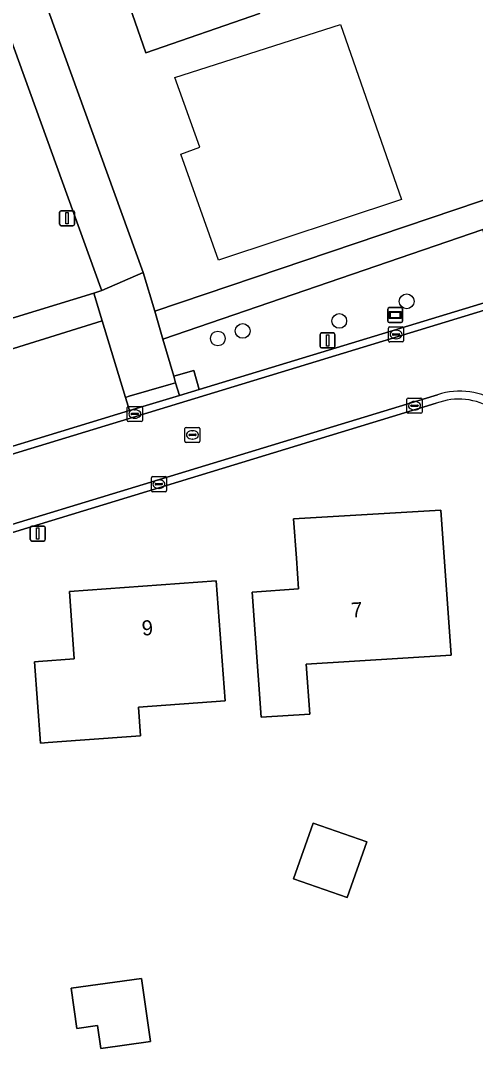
# Model space of a CAD drawing. Extents: x 162661 to 163484, y 380247 to 381230.
# Drawn here: x 162984 to 163014.3, y 380733.3 to 380801.7 of the extents above; entities that cross this region are included whole.
import ezdxf

# ---------------------------------------------------------------- set-up
doc = ezdxf.new("R2010")
doc.units = 0
for name, color, linetype in [('IMGEO_Berm_halfverhard', 7, 'Continuous'), ('IMGEO_Boom', 7, 'Continuous'), ('IMGEO_Erf', 7, 'Continuous'), ('IMGEO_Groenvoorziening', 7, 'Continuous'), ('IMGEO_Kolk', 7, 'Continuous'), ('IMGEO_Lichtmast', 7, 'Continuous'), ('IMGEO_Pand', 7, 'Continuous'), ('IMGEO_Pand_nummerreeks', 7, 'Continuous'), ('IMGEO_Pand_vergunning_verleend', 7, 'Continuous'), ('IMGEO_Parkeervlak_open', 7, 'Continuous'), ('IMGEO_Rijbaan_lokaal_gesloten', 7, 'Continuous'), ('IMGEO_Rijbaan_lokaal_open', 7, 'Continuous'), ('IMGEO_Rioolput', 7, 'Continuous'), ('IMGEO_Voetpad_open', 7, 'Continuous'), ('IMGEO_Wegwijzer', 7, 'Continuous')]:
    doc.layers.add(name, color=color, linetype=linetype)

msp = doc.modelspace()

# ---------------------------------------------------------------- linework, layer by layer
at = {"layer": 'IMGEO_Berm_halfverhard'}
msp.add_lwpolyline([(162995.544, 380778.396), (162994.204, 380778.017), (162994.332, 380777.579), (162994.583, 380776.73), (162995.902, 380777.131)], close=True, dxfattribs=at)
at = {"layer": 'IMGEO_Boom'}
for centre in [(163009.697, 380782.988), (163005.212, 380781.684), (162997.137, 380780.52), (162998.789, 380781.023)]:
    msp.add_circle(centre, 0.489, dxfattribs=at)
at = {"layer": 'IMGEO_Erf'}
for points in [[(162926.406, 380762.393), (162971.79, 380776.161), (162971.978, 380776.218), (162971.296, 380778.555), (162965.296, 380803.494), (162959.948, 380825.491), (162975.656, 380830.504), (162983.99, 380807.505), (162992.18, 380784.912), (162992.937, 380782.334), (163021.239, 380791.885)], [(163011.662, 380776.211), (162963.124, 380761.423)]]:
    msp.add_lwpolyline(points, dxfattribs=at)
for points in [[(162989.136, 380808.763), (162998.492, 380812.004), (162999.811, 380808.197), (162998.015, 380807.574), (162999.904, 380802.121), (162992.343, 380799.502)], [(163002.362, 380765.911), (163002.176, 380768.534), (163011.975, 380769.115), (163012.657, 380759.471), (163003.019, 380758.872), (163003.253, 380755.563), (163000.013, 380755.362), (162999.426, 380763.668), (163002.505, 380763.886)], [(162984.942, 380759.04), (162985.218, 380759.06), (162987.587, 380759.234), (162987.26, 380763.699), (162997.035, 380764.416), (162997.62, 380756.437), (162991.866, 380756.015), (162992.003, 380754.12), (162987.984, 380753.826), (162985.851, 380753.67), (162985.614, 380753.653), (162985.338, 380753.632)], [(163002.177, 380744.611), (163003.478, 380748.311), (163007.042, 380747.058), (163005.741, 380743.358)], [(162987.383, 380737.337), (162992.069, 380737.992), (162992.655, 380733.798), (162989.347, 380733.336), (162989.136, 380734.853), (162987.757, 380734.66)]]:
    msp.add_lwpolyline(points, close=True, dxfattribs=at)
msp.add_arc((163013.172, 380772.236), 4.253, 3.53872, 110.80283, dxfattribs=at)
at = {"layer": 'IMGEO_Groenvoorziening'}
msp.add_lwpolyline([(162964.008, 380821.602), (162968.622, 380802.474), (162974.235, 380779.267), (162974.547, 380779.362), (162974.605, 380779.176), (162988.89, 380783.54), (162989.418, 380783.701), (162989.357, 380783.869), (162980.643, 380807.906), (162974.496, 380824.924)], dxfattribs=at)
msp.add_lwpolyline([(163016.15, 380783.294), (163014.767, 380787.754), (162993.48, 380780.484), (162994.204, 380778.017), (162995.544, 380778.396), (162995.902, 380777.131)], close=True, dxfattribs=at)
at = {"layer": 'IMGEO_Kolk'}
for p, q in [((163008.492, 380780.361), (163008.492, 380781.213)), ((163008.567, 380781.287), (163009.419, 380781.287)), ((163008.98, 380781.067), (163009.005, 380781.067)), ((163009.493, 380781.213), (163009.493, 380780.361)), ((163009.419, 380780.287), (163008.567, 380780.287)), ((163008.751, 380780.781), (163008.751, 380780.793)), ((163009.189, 380780.744), (163008.791, 380780.744)), ((163008.794, 380780.83), (163009.192, 380780.83)), ((163009.003, 380780.507), (163008.978, 380780.507)), ((163009.235, 380780.793), (163009.235, 380780.781)), ((163009.717, 380775.627), (163009.717, 380776.479)), ((163009.792, 380776.553), (163010.644, 380776.553)), ((163010.019, 380776.096), (163010.417, 380776.096)), ((163010.205, 380776.333), (163010.23, 380776.333)), ((163010.718, 380776.479), (163010.718, 380775.627)), ((162991.116, 380775.077), (162991.116, 380775.929)), ((162991.191, 380776.003), (162992.043, 380776.003)), ((162991.375, 380775.497), (162991.375, 380775.509)), ((162991.813, 380775.46), (162991.415, 380775.46)), ((162991.418, 380775.546), (162991.816, 380775.546)), ((162991.604, 380775.783), (162991.629, 380775.783)), ((162991.859, 380775.509), (162991.859, 380775.497)), ((162992.117, 380775.929), (162992.117, 380775.077)), ((163010.644, 380775.553), (163009.792, 380775.553)), ((163009.976, 380776.047), (163009.976, 380776.059)), ((163010.414, 380776.01), (163010.016, 380776.01)), ((163010.228, 380775.773), (163010.203, 380775.773)), ((163010.46, 380776.059), (163010.46, 380776.047)), ((162992.043, 380775.003), (162991.191, 380775.003)), ((162991.627, 380775.223), (162991.602, 380775.223)), ((162992.792, 380771.339), (162993.644, 380771.339)), ((162992.717, 380770.413), (162992.717, 380771.265)), ((162992.976, 380770.833), (162992.976, 380770.845)), ((162993.414, 380770.796), (162993.016, 380770.796)), ((162993.019, 380770.882), (162993.417, 380770.882)), ((162993.205, 380771.119), (162993.23, 380771.119)), ((162993.46, 380770.845), (162993.46, 380770.833)), ((162993.718, 380771.265), (162993.718, 380770.413)), ((162993.644, 380770.339), (162992.792, 380770.339)), ((162993.228, 380770.559), (162993.203, 380770.559))]:
    msp.add_line(p, q, dxfattribs=at)
for points in [[(163008.492, 380780.361), (163008.492, 380781.213)], [(163008.567, 380781.287), (163009.419, 380781.287)], [(163009.493, 380781.213), (163009.493, 380780.361)], [(163009.419, 380780.287), (163008.567, 380780.287)], [(163009.717, 380775.627), (163009.717, 380776.479)], [(163009.792, 380776.553), (163010.644, 380776.553)], [(163010.718, 380776.479), (163010.718, 380775.627)], [(162991.116, 380775.077), (162991.116, 380775.929)], [(162991.191, 380776.003), (162992.043, 380776.003)], [(162992.117, 380775.929), (162992.117, 380775.077)], [(163010.644, 380775.553), (163009.792, 380775.553)], [(162992.043, 380775.003), (162991.191, 380775.003)], [(162992.792, 380771.339), (162993.644, 380771.339)], [(162992.717, 380770.413), (162992.717, 380771.265)], [(162993.718, 380771.265), (162993.718, 380770.413)], [(162993.644, 380770.339), (162992.792, 380770.339)]]:
    msp.add_lwpolyline(points, dxfattribs=at)
for centre, radius, start, end in [((163008.569, 380781.211), 0.0765, 91.55205, 178.44795), ((163008.569, 380781.211), 0.0765, 91.55205, 178.44795), ((163009.417, 380781.211), 0.0765, 1.55205, 88.44795), ((163009.417, 380781.211), 0.0765, 1.55205, 88.44795), ((163008.569, 380780.363), 0.0765, 181.55205, 268.44795), ((163008.569, 380780.363), 0.0765, 181.55205, 268.44795), ((163008.791, 380780.79), 0.0403, 85.87752, 175.75265), ((163008.788, 380780.78), 0.0366, 178.93798, 274.71019), ((163009.192, 380780.787), 0.043, 264.86636, 352.45326), ((163009.196, 380780.792), 0.0386, 1.73085, 96.63898), ((163009.417, 380780.363), 0.0765, 271.55205, 358.44795), ((163009.417, 380780.363), 0.0765, 271.55205, 358.44795), ((163009.794, 380776.477), 0.0765, 91.55205, 178.44795), ((163009.794, 380776.477), 0.0765, 91.55205, 178.44795), ((163010.016, 380776.056), 0.0403, 85.87752, 175.75265), ((163010.421, 380776.058), 0.0386, 1.73085, 96.63898), ((163010.642, 380776.477), 0.0765, 1.55205, 88.44795), ((163010.642, 380776.477), 0.0765, 1.55205, 88.44795), ((162991.193, 380775.927), 0.0765, 91.55205, 178.44795), ((162991.193, 380775.927), 0.0765, 91.55205, 178.44795), ((162991.415, 380775.506), 0.0403, 85.87752, 175.75265), ((162991.412, 380775.496), 0.0366, 178.93798, 274.71019), ((162991.816, 380775.503), 0.043, 264.86636, 352.45326), ((162991.82, 380775.508), 0.0386, 1.73085, 96.63898), ((162992.041, 380775.927), 0.0765, 1.55205, 88.44795), ((162992.041, 380775.927), 0.0765, 1.55205, 88.44795), ((163009.794, 380775.629), 0.0765, 181.55205, 268.44795), ((163009.794, 380775.629), 0.0765, 181.55205, 268.44795), ((163010.013, 380776.046), 0.0366, 178.93798, 274.71019), ((163010.417, 380776.053), 0.043, 264.86636, 352.45326), ((163010.642, 380775.629), 0.0765, 271.55205, 358.44795), ((163010.642, 380775.629), 0.0765, 271.55205, 358.44795), ((162991.193, 380775.079), 0.0765, 181.55205, 268.44795), ((162991.193, 380775.079), 0.0765, 181.55205, 268.44795), ((162992.041, 380775.079), 0.0765, 271.55205, 358.44795), ((162992.041, 380775.079), 0.0765, 271.55205, 358.44795), ((162992.794, 380771.263), 0.0765, 91.55205, 178.44795), ((162992.794, 380771.263), 0.0765, 91.55205, 178.44795), ((162993.642, 380771.263), 0.0765, 1.55205, 88.44795), ((162993.642, 380771.263), 0.0765, 1.55205, 88.44795), ((162993.016, 380770.842), 0.0403, 85.87752, 175.75265), ((162993.013, 380770.832), 0.0366, 178.93798, 274.71019), ((162993.417, 380770.839), 0.043, 264.86636, 352.45326), ((162993.421, 380770.844), 0.0386, 1.73085, 96.63898), ((162992.794, 380770.415), 0.0765, 181.55205, 268.44795), ((162992.794, 380770.415), 0.0765, 181.55205, 268.44795), ((162993.642, 380770.415), 0.0765, 271.55205, 358.44795), ((162993.642, 380770.415), 0.0765, 271.55205, 358.44795)]:
    msp.add_arc(centre, radius, start, end, dxfattribs=at)
for centre, major_axis, ratio, start_param, end_param in [((163008.979, 380780.787), (-0.387, 0.002), 0.722429, 4.712389, 7.853982), ((163009.004, 380780.787), (-0.39, 0.002), 0.717154, 1.570796, 4.712389), ((163010.204, 380776.053), (-0.387, 0.002), 0.722429, 4.712389, 7.853982), ((163010.229, 380776.053), (-0.39, 0.002), 0.717154, 1.570796, 4.712389), ((162991.603, 380775.503), (-0.387, 0.002), 0.722429, 4.712389, 7.853982), ((162991.628, 380775.503), (-0.39, 0.002), 0.717154, 1.570796, 4.712389), ((162993.204, 380770.839), (-0.387, 0.002), 0.722429, 4.712389, 7.853982), ((162993.229, 380770.839), (-0.39, 0.002), 0.717154, 1.570796, 4.712389)]:
    msp.add_ellipse(centre, major_axis=major_axis, ratio=ratio, start_param=start_param, end_param=end_param, dxfattribs=at)
at = {"layer": 'IMGEO_Lichtmast'}
for p, q in [((162986.613, 380788.113), (162986.613, 380788.913)), ((162986.613, 380788.913), (162986.613, 380788.113)), ((162986.713, 380789.013), (162987.503, 380789.013)), ((162987.503, 380789.013), (162986.713, 380789.013)), ((162987.603, 380788.913), (162987.603, 380788.113)), ((162987.603, 380788.113), (162987.603, 380788.913)), ((162987.503, 380788.013), (162986.713, 380788.013)), ((162986.713, 380788.013), (162987.503, 380788.013)), ((163004.039, 380780.89), (163004.829, 380780.89)), ((163004.829, 380780.89), (163004.039, 380780.89)), ((163003.939, 380779.99), (163003.939, 380780.79)), ((163003.939, 380780.79), (163003.939, 380779.99)), ((163004.929, 380780.79), (163004.929, 380779.99)), ((163004.929, 380779.99), (163004.929, 380780.79)), ((163004.829, 380779.89), (163004.039, 380779.89)), ((163004.039, 380779.89), (163004.829, 380779.89)), ((162984.664, 380767.156), (162984.664, 380767.956)), ((162984.664, 380767.956), (162984.664, 380767.156)), ((162984.764, 380768.056), (162985.554, 380768.056)), ((162985.554, 380768.056), (162984.764, 380768.056)), ((162985.654, 380767.956), (162985.654, 380767.156)), ((162985.654, 380767.156), (162985.654, 380767.956)), ((162985.554, 380767.056), (162984.764, 380767.056)), ((162984.764, 380767.056), (162985.554, 380767.056))]:
    msp.add_line(p, q, dxfattribs=at)
for points in [[(162987.033, 380788.888), (162987.183, 380788.888), (162987.183, 380788.138), (162987.033, 380788.138), (162987.033, 380788.888)], [(163004.359, 380780.765), (163004.509, 380780.765), (163004.509, 380780.015), (163004.359, 380780.015), (163004.359, 380780.765)], [(162985.084, 380767.931), (162985.234, 380767.931), (162985.234, 380767.181), (162985.084, 380767.181), (162985.084, 380767.931)]]:
    msp.add_lwpolyline(points, dxfattribs=at)
for centre, start, end in [((162986.713, 380788.913), 90, 180), ((162986.713, 380788.913), 90, 180), ((162987.503, 380788.913), 0, 90), ((162987.503, 380788.913), 360, 90), ((162986.713, 380788.113), 180, 270), ((162986.713, 380788.113), 180, 270), ((162987.503, 380788.113), 270, 0), ((162987.503, 380788.113), 270, 0), ((163004.039, 380780.79), 90, 180), ((163004.039, 380780.79), 90, 180), ((163004.829, 380780.79), 0, 90), ((163004.829, 380780.79), 360, 90), ((163004.039, 380779.99), 180, 270), ((163004.039, 380779.99), 180, 270), ((163004.829, 380779.99), 270, 0), ((163004.829, 380779.99), 270, 0), ((162984.764, 380767.956), 90, 180), ((162984.764, 380767.956), 90, 180), ((162985.554, 380767.956), 0, 90), ((162985.554, 380767.956), 360, 90), ((162984.764, 380767.156), 180, 270), ((162984.764, 380767.156), 180, 270), ((162985.554, 380767.156), 270, 0), ((162985.554, 380767.156), 270, 0)]:
    msp.add_arc(centre, 0.1, start, end, dxfattribs=at)
at = {"layer": 'IMGEO_Pand'}
for points in [[(162992.343, 380799.502), (162999.904, 380802.121), (162998.015, 380807.574), (162999.811, 380808.197), (162998.492, 380812.004), (162989.136, 380808.763)], [(163011.975, 380769.115), (163002.176, 380768.534), (163002.362, 380765.911), (163002.505, 380763.886), (162999.426, 380763.668), (163000.013, 380755.362), (163003.253, 380755.563), (163003.019, 380758.872), (163012.657, 380759.471)], [(162997.035, 380764.416), (162987.26, 380763.699), (162987.587, 380759.234), (162985.218, 380759.06), (162984.942, 380759.04), (162985.338, 380753.632), (162985.614, 380753.653), (162985.851, 380753.67), (162987.984, 380753.826), (162992.003, 380754.12), (162991.866, 380756.015), (162997.62, 380756.437)], [(163002.177, 380744.611), (163005.741, 380743.358), (163007.042, 380747.058), (163003.478, 380748.311)], [(162987.383, 380737.337), (162987.757, 380734.66), (162989.136, 380734.853), (162989.347, 380733.336), (162992.655, 380733.798), (162992.069, 380737.992)]]:
    msp.add_lwpolyline(points, close=True, dxfattribs=at)
at = {"layer": 'IMGEO_Pand_vergunning_verleend'}
msp.add_lwpolyline([(162994.288, 380797.865), (163005.301, 380801.399), (163009.345, 380789.757), (162997.187, 380785.73), (162994.667, 380792.767), (162995.949, 380793.226)], close=True, dxfattribs=at)
at = {"layer": 'IMGEO_Parkeervlak_open'}
msp.add_lwpolyline([(162990.992, 380776.609), (162989.449, 380781.698), (162975.199, 380777.265), (162976.762, 380772.242), (162977.033, 380771.392), (162991.253, 380775.737)], close=True, dxfattribs=at)
at = {"layer": 'IMGEO_Rijbaan_lokaal_gesloten'}
for points in [[(163016.688, 380782.965), (162948.75, 380762.271), (162947.7, 380760.456)], [(163011.53, 380776.704), (163011.738, 380776.78)], [(162960.12, 380762.434), (162961.731, 380761.565), (163011.53, 380776.704)]]:
    msp.add_lwpolyline(points, dxfattribs=at)
msp.add_arc((163013.228, 380772.334), 4.689, 1.36553, 108.5335, dxfattribs=at)
at = {"layer": 'IMGEO_Rijbaan_lokaal_open'}
for points in [[(163017.65, 380783.769), (163016.926, 380783.534), (163016.492, 380783.398), (163016.15, 380783.294), (162995.902, 380777.131), (162994.583, 380776.73), (162991.253, 380775.737), (162977.033, 380771.392), (162973.725, 380770.368), (162972.355, 380769.952), (162970.637, 380769.431), (162949.808, 380763.113)], [(162948.75, 380762.271), (163016.688, 380782.965)], [(163011.738, 380776.78), (163011.53, 380776.704), (162961.731, 380761.565)], [(162963.124, 380761.423), (163011.662, 380776.211)]]:
    msp.add_lwpolyline(points, dxfattribs=at)
for centre, radius, start, end in [((163013.228, 380772.334), 4.689, 1.36553, 108.5335), ((163013.172, 380772.236), 4.253, 3.53872, 110.80283)]:
    msp.add_arc(centre, radius, start, end, dxfattribs=at)
at = {"layer": 'IMGEO_Rioolput'}
for p, q in [((162994.949, 380773.686), (162994.949, 380774.538)), ((162995.024, 380774.612), (162995.876, 380774.612)), ((162995.208, 380774.106), (162995.208, 380774.118)), ((162995.646, 380774.069), (162995.248, 380774.069)), ((162995.251, 380774.155), (162995.649, 380774.155)), ((162995.437, 380774.392), (162995.462, 380774.392)), ((162995.692, 380774.118), (162995.692, 380774.106)), ((162995.95, 380774.538), (162995.95, 380773.686)), ((162995.876, 380773.612), (162995.024, 380773.612)), ((162995.46, 380773.832), (162995.435, 380773.832))]:
    msp.add_line(p, q, dxfattribs=at)
for points in [[(162994.949, 380773.686), (162994.949, 380774.538)], [(162995.024, 380774.612), (162995.876, 380774.612)], [(162995.95, 380774.538), (162995.95, 380773.686)], [(162995.876, 380773.612), (162995.024, 380773.612)]]:
    msp.add_lwpolyline(points, dxfattribs=at)
for centre, radius, start, end in [((162995.026, 380774.536), 0.0765, 91.55205, 178.44795), ((162995.026, 380774.536), 0.0765, 91.55205, 178.44795), ((162995.248, 380774.115), 0.0403, 85.87752, 175.75265), ((162995.245, 380774.105), 0.0366, 178.93798, 274.71019), ((162995.649, 380774.112), 0.043, 264.86636, 352.45326), ((162995.653, 380774.117), 0.0386, 1.73085, 96.63898), ((162995.874, 380774.536), 0.0765, 1.55205, 88.44795), ((162995.874, 380774.536), 0.0765, 1.55205, 88.44795), ((162995.026, 380773.688), 0.0765, 181.55205, 268.44795), ((162995.026, 380773.688), 0.0765, 181.55205, 268.44795), ((162995.874, 380773.688), 0.0765, 271.55205, 358.44795), ((162995.874, 380773.688), 0.0765, 271.55205, 358.44795)]:
    msp.add_arc(centre, radius, start, end, dxfattribs=at)
for centre, major_axis, ratio, start_param, end_param in [((162995.436, 380774.112), (-0.387, 0.002), 0.722429, 4.712389, 7.853982), ((162995.461, 380774.112), (-0.39, 0.002), 0.717154, 1.570796, 4.712389)]:
    msp.add_ellipse(centre, major_axis=major_axis, ratio=ratio, start_param=start_param, end_param=end_param, dxfattribs=at)
at = {"layer": 'IMGEO_Voetpad_open'}
msp.add_lwpolyline([(162974.496, 380824.924), (162980.643, 380807.906), (162989.357, 380783.869), (162989.418, 380783.701), (162992.18, 380784.912), (162983.99, 380807.505), (162975.656, 380830.504), (162959.948, 380825.491), (162965.296, 380803.494), (162971.296, 380778.555), (162974.235, 380779.267), (162968.622, 380802.474), (162964.008, 380821.602)], dxfattribs=at)
for points in [[(163030.961, 380793.075), (163057.8, 380804.399), (163057.075, 380806.099), (163052.818, 380804.317), (163051.126, 380803.589), (163038.763, 380798.374), (163037.38, 380797.789), (163030.119, 380794.72), (163024.587, 380792.93), (163021.339, 380791.92), (163021.239, 380791.885), (162992.937, 380782.334), (162993.48, 380780.484), (163014.767, 380787.754), (163015.496, 380788.003), (163016.21, 380788.247), (163016.973, 380788.507), (163021.596, 380790.086), (163023.438, 380790.648), (163024.739, 380786.977), (163024.877, 380786.639), (163026.545, 380787.336), (163026.413, 380787.66), (163025.188, 380791.197)], [(162992.937, 380782.334), (162992.18, 380784.912), (162989.418, 380783.701), (162988.89, 380783.54), (162989.449, 380781.698), (162990.992, 380776.609), (162991.238, 380776.68), (162993.861, 380777.442), (162994.332, 380777.579), (162994.204, 380778.017), (162993.48, 380780.484)], [(162989.449, 380781.698), (162988.89, 380783.54), (162974.605, 380779.176), (162975.199, 380777.265)], [(162990.992, 380776.609), (162991.253, 380775.737), (162994.583, 380776.73), (162994.332, 380777.579), (162993.861, 380777.442), (162991.238, 380776.68)]]:
    msp.add_lwpolyline(points, close=True, dxfattribs=at)
at = {"layer": 'IMGEO_Wegwijzer'}
for p, q in [((163008.435, 380781.675), (163008.435, 380782.475)), ((163008.435, 380782.475), (163008.435, 380781.675)), ((163008.535, 380782.575), (163009.325, 380782.575)), ((163009.325, 380782.575), (163008.535, 380782.575)), ((163009.425, 380782.475), (163009.425, 380781.675)), ((163009.425, 380781.675), (163009.425, 380782.475)), ((163009.325, 380781.575), (163008.535, 380781.575)), ((163008.535, 380781.575), (163009.325, 380781.575))]:
    msp.add_line(p, q, dxfattribs=at)
for points in [[(163008.536, 380782.307), (163009.324, 380782.307), (163009.324, 380781.843), (163008.536, 380781.843), (163008.536, 380782.307)], [(163008.601, 380782.242), (163008.601, 380781.908), (163009.259, 380781.908), (163009.259, 380782.242), (163008.601, 380782.242)]]:
    msp.add_lwpolyline(points, dxfattribs=at)
for centre, start, end in [((163008.535, 380782.475), 90, 180), ((163008.535, 380782.475), 90, 180), ((163009.325, 380782.475), 0, 90), ((163009.325, 380782.475), 360, 90), ((163008.535, 380781.675), 180, 270), ((163008.535, 380781.675), 180, 270), ((163009.325, 380781.675), 270, 0), ((163009.325, 380781.675), 270, 0)]:
    msp.add_arc(centre, 0.1, start, end, dxfattribs=at)

# ---------------------------------------------------------------- texts
at = {"layer": 'IMGEO_Pand_nummerreeks'}
for s, rotation, p in [('7', 3.55661, (163006.035, 380761.964)), ('9', 4.19405, (162992.113, 380760.766))]:
    msp.add_text(s, height=1, rotation=rotation, dxfattribs=at).set_placement(p)

doc.saveas('drawing.dxf')
